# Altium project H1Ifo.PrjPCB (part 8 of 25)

## Sheet IfoIsc3.SchDoc: D1800185
size C; Engineer: Daniel Sigg; DocumentNumber: 7; Revision: 4; SheetNumber: 7; SheetTotal: 11
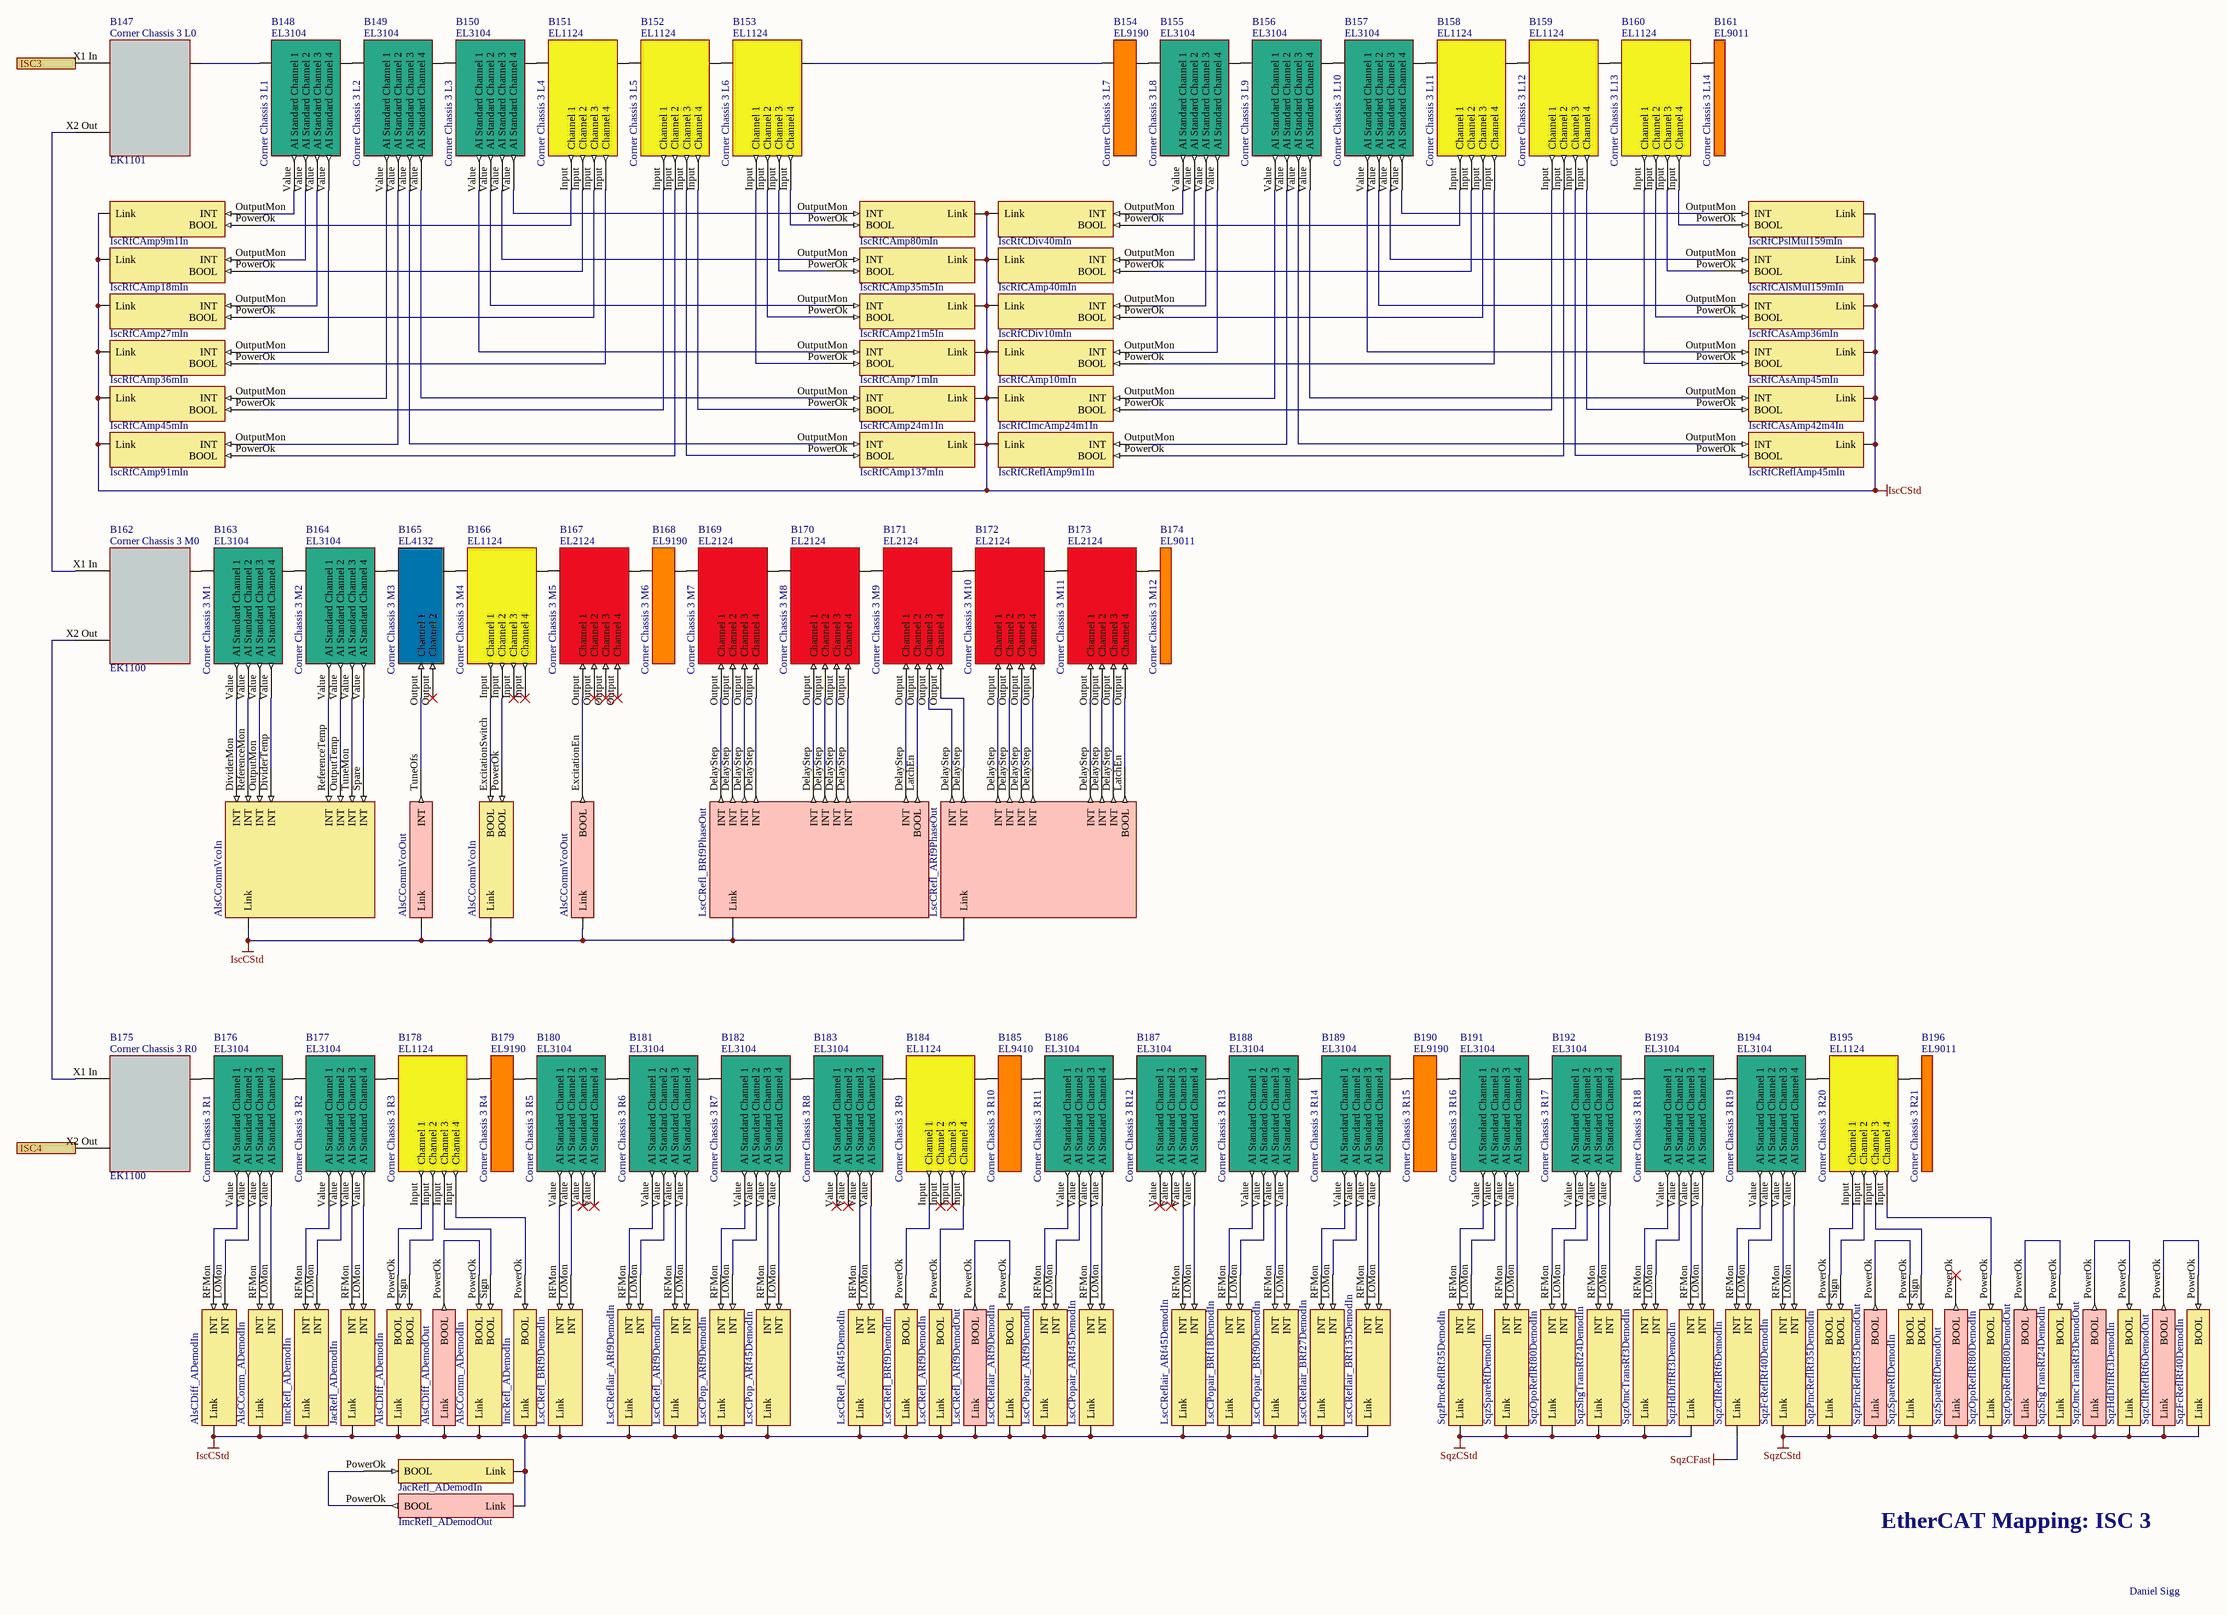
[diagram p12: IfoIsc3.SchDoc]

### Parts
B147  Corner Chassis 3 L0  Part Number: EK1101  (mechanical)
B148  Corner Chassis 3 L1  Part Number: EL3104  (mechanical)
B149  Corner Chassis 3 L2  Part Number: EL3104  (mechanical)
B150  Corner Chassis 3 L3  Part Number: EL3104  (mechanical)
B151  Corner Chassis 3 L4  Part Number: EL1124  (mechanical)
B152  Corner Chassis 3 L5  Part Number: EL1124  (mechanical)
B153  Corner Chassis 3 L6  Part Number: EL1124  (mechanical)
B154  Corner Chassis 3 L7  Part Number: EL9190  (mechanical)
B155  Corner Chassis 3 L8  Part Number: EL3104  (mechanical)
B156  Corner Chassis 3 L9  Part Number: EL3104  (mechanical)
B157  Corner Chassis 3 L10  Part Number: EL3104  (mechanical)
B158  Corner Chassis 3 L11  Part Number: EL1124  (mechanical)
B159  Corner Chassis 3 L12  Part Number: EL1124  (mechanical)
B160  Corner Chassis 3 L13  Part Number: EL1124  (mechanical)
B161  Corner Chassis 3 L14  Part Number: EL9011  (mechanical)
B162  Corner Chassis 3 M0  Part Number: EK1100  (mechanical)
B163  Corner Chassis 3 M1  Part Number: EL3104  (mechanical)
B164  Corner Chassis 3 M2  Part Number: EL3104  (mechanical)
B165  Corner Chassis 3 M3  Part Number: EL4132  (mechanical)
B166  Corner Chassis 3 M4  Part Number: EL1124  (mechanical)
B167  Corner Chassis 3 M5  Part Number: EL2124  (mechanical)
B168  Corner Chassis 3 M6  Part Number: EL9190  (mechanical)
B169  Corner Chassis 3 M7  Part Number: EL2124  (mechanical)
B170  Corner Chassis 3 M8  Part Number: EL2124  (mechanical)
B171  Corner Chassis 3 M9  Part Number: EL2124  (mechanical)
B172  Corner Chassis 3 M10  Part Number: EL2124  (mechanical)
B173  Corner Chassis 3 M11  Part Number: EL2124  (mechanical)
B174  Corner Chassis 3 M12  Part Number: EL9011  (mechanical)
B175  Corner Chassis 3 R0  Part Number: EK1100  (mechanical)
B176  Corner Chassis 3 R1  Part Number: EL3104  (mechanical)
B177  Corner Chassis 3 R2  Part Number: EL3104  (mechanical)
B178  Corner Chassis 3 R3  Part Number: EL1124  (mechanical)
B179  Corner Chassis 3 R4  Part Number: EL9190  (mechanical)
B180  Corner Chassis 3 R5  Part Number: EL3104  (mechanical)
B181  Corner Chassis 3 R6  Part Number: EL3104  (mechanical)
B182  Corner Chassis 3 R7  Part Number: EL3104  (mechanical)
B183  Corner Chassis 3 R8  Part Number: EL3104  (mechanical)
B184  Corner Chassis 3 R9  Part Number: EL1124  (mechanical)
B185  Corner Chassis 3 R10  Part Number: EL9410  (mechanical)
B186  Corner Chassis 3 R11  Part Number: EL3104  (mechanical)
B187  Corner Chassis 3 R12  Part Number: EL3104  (mechanical)
B188  Corner Chassis 3 R13  Part Number: EL3104  (mechanical)
B189  Corner Chassis 3 R14  Part Number: EL3104  (mechanical)
B190  Corner Chassis 3 R15  Part Number: EL9190  (mechanical)
B191  Corner Chassis 3 R16  Part Number: EL3104  (mechanical)
B192  Corner Chassis 3 R17  Part Number: EL3104  (mechanical)
B193  Corner Chassis 3 R18  Part Number: EL3104  (mechanical)
B194  Corner Chassis 3 R19  Part Number: EL3104  (mechanical)
B195  Corner Chassis 3 R20  Part Number: EL1124  (mechanical)
B196  Corner Chassis 3 R21  Part Number: EL9011  (mechanical)
V125  AlsCDiff_ADemodIn  (parts A,B of 2)  (no BOM)
V126  AlsCComm_ADemodIn  (parts A,B of 2)  (no BOM)
V127  ImcRefl_ADemodIn  (parts A,B of 2)  (no BOM)
V128  JacRefl_ADemodIn  (parts A,B of 2)  (no BOM)
V131  LscCReflair_ARf9DemodIn  (parts A,B of 2)  (no BOM)
V132  LscCRefl_ARf9DemodIn  (parts A,B of 2)  (no BOM)
V149  AlsCCommVcoIn  (parts A,B of 2)  (no BOM)
V153  SqzOpoReflRf80DemodIn  (parts A,B of 2)  (no BOM)
V154  SqzShgTransRf24DemodIn  (parts A,B of 2)  (no BOM)
V169  SqzHdDiffRf3DemodIn  (parts A,B of 2)  (no BOM)
V171  SqzFcReflRf40DemodIn  (parts A,B of 2)  (no BOM)
V210  IscRfCAmp9m1In  (no BOM)
V227  IscRfCAmp80mIn  (no BOM)
V236  IscRfCDiv40mIn  (no BOM)
V237  IscRfCPslMul159mIn  (no BOM)
V239  IscRfCAmp18mIn  (no BOM)
V240  IscRfCAmp35m5In  (no BOM)
V241  IscRfCAmp40mIn  (no BOM)
V242  IscRfCAlsMul159mIn  (no BOM)
V243  IscRfCAmp27mIn  (no BOM)
V244  IscRfCAmp21m5In  (no BOM)
V245  IscRfCDiv10mIn  (no BOM)
V246  IscRfCAsAmp36mIn  (no BOM)
V247  IscRfCAmp36mIn  (no BOM)
V248  IscRfCAmp71mIn  (no BOM)
V249  IscRfCAmp10mIn  (no BOM)
V250  IscRfCAsAmp45mIn  (no BOM)
V251  IscRfCAmp45mIn  (no BOM)
V252  IscRfCAmp24m1In  (no BOM)
V253  IscRfCImcAmp24m1In  (no BOM)
V254  IscRfCAsAmp42m4In  (no BOM)
V255  IscRfCAmp91mIn  (no BOM)
V256  IscRfCAmp137mIn  (no BOM)
V257  IscRfCReflAmp9m1In  (no BOM)
V260  IscRfCReflAmp45mIn  (no BOM)
V261  AlsCCommVcoOut  (parts A,B of 2)  (no BOM)
V264  LscCRefl_BRf9PhaseOut  (no BOM)
V265  LscCRefl_ARf9PhaseOut  (no BOM)
V266  AlsCDiff_ADemodOut  (no BOM)
V267  ImcRefl_ADemodOut  (no BOM)
V268  LscCPop_ARf9DemodIn  (no BOM)
V269  LscCPop_ARf45DemodIn  (no BOM)
V270  LscCRefl_ARf45DemodIn  (no BOM)
V271  LscCRefl_ARf9DemodOut  (no BOM)
V280  LscCPopair_ARf9DemodIn  (no BOM)
V281  LscCPopair_ARf45DemodIn  (no BOM)
V282  LscCReflair_ARf45DemodIn  (no BOM)
V283  LscCPopair_BRf18DemodIn  (no BOM)
V284  LscCPopair_BRf90DemodIn  (no BOM)
V285  LscCReflair_BRf27DemodIn  (no BOM)
V286  LscCReflair_BRf135DemodIn  (no BOM)
V287  SqzOmcTransRf3DemodIn  (no BOM)
V288  SqzClfReflRf6DemodIn  (no BOM)
V293  SqzPmcReflRf35DemodOut  (no BOM)
V294  SqzSpareRfDemodOut  (no BOM)
V295  SqzOpoReflRf80DemodOut  (no BOM)
V296  SqzOmcTransRf3DemodOut  (no BOM)
V299  SqzClfReflRf6DemodOut  (no BOM)
V680  SqzPmcReflRf35DemodIn  (parts A,B of 2)  (no BOM)
V681  SqzSpareRfDemodIn  (parts A,B of 2)  (no BOM)
V876  LscCRefl_BRf9DemodIn  (parts A,B of 2)  (no BOM)

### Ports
ISC3, ISC4

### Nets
IscCStd: V125.0(Link) V125.1(Link) V126.0(Link) V126.1(Link) V127.0(Link) V127.1(Link) V128.0(Link) V128.1(Link) V131.0(Link) V131.1(Link) V132.0(Link) V132.1(Link) V149.0(Link) V149.1(Link) V210.?1(Link) V227.?1(Link) V236.?1(Link) V237.?1(Link) V239.?1(Link) V240.?1(Link) V241.?1(Link) V242.?1(Link) V243.?1(Link) V244.?1(Link) V245.?1(Link) V246.?1(Link) V247.?1(Link) V248.?1(Link) V249.?1(Link) V250.?1(Link) V251.?1(Link) V252.?1(Link) V253.?1(Link) V254.?1(Link) V255.?1(Link) V256.?1(Link) V257.?1(Link) V260.?1(Link) V261.0(Link) V261.1(Link) V264.?1(Link) V265.?1(Link) V266.?1(Link) V267.?1(Link) V268.0(Link) V269.0(Link) V270.0(Link) V271.?1(Link) V280.0(Link) V281.0(Link) V282.0(Link) V283.0(Link) V284.0(Link) V285.0(Link) V286.0(Link) V876.0(Link) V876.1(Link)
SqzCFast: V288.0(Link)
SqzCStd: V153.0(Link) V153.1(Link) V154.0(Link) V154.1(Link) V169.0(Link) V169.1(Link) V171.0(Link) V171.1(Link) V287.0(Link) V293.?1(Link) V294.?1(Link) V295.?1(Link) V296.?1(Link) V299.?1(Link) V680.0(Link) V680.1(Link) V681.0(Link) V681.1(Link)
NetB107_X2 Out: B147.X1_In(A) ; port ISC3
NetB147_Ebus: B147.Ebus(B) B148.Ebus(A)
NetB147_X2 Out: B147.X2_Out(C) B162.X1_In(A)
NetB148_Ebus: B148.Ebus(B) B149.Ebus(A)
NetB148_Value: B148.Value(AI_Standard_Channel_1) V210.OutputMon(INT)
NetB148_Value: B148.Value(AI_Standard_Channel_2) V239.OutputMon(INT)  [a separate net that carries the same name]
NetB148_Value: B148.Value(AI_Standard_Channel_3) V243.OutputMon(INT)  [a separate net that carries the same name]
NetB148_Value: B148.Value(AI_Standard_Channel_4) V247.OutputMon(INT)  [a separate net that carries the same name]
NetB149_Ebus: B149.Ebus(B) B150.Ebus(A)
NetB149_Value: B149.Value(AI_Standard_Channel_1) V251.OutputMon(INT)
NetB149_Value: B149.Value(AI_Standard_Channel_2) V255.OutputMon(INT)  [a separate net that carries the same name]
NetB149_Value: B149.Value(AI_Standard_Channel_3) V256.OutputMon(INT)  [a separate net that carries the same name]
NetB149_Value: B149.Value(AI_Standard_Channel_4) V252.OutputMon(INT)  [a separate net that carries the same name]
NetB150_Ebus: B150.Ebus(B) B151.Ebus(A)
NetB150_Value: B150.Value(AI_Standard_Channel_1) V248.OutputMon(INT)
NetB150_Value: B150.Value(AI_Standard_Channel_2) V244.OutputMon(INT)  [a separate net that carries the same name]
NetB150_Value: B150.Value(AI_Standard_Channel_3) V240.OutputMon(INT)  [a separate net that carries the same name]
NetB150_Value: B150.Value(AI_Standard_Channel_4) V227.OutputMon(INT)  [a separate net that carries the same name]
NetB151_Ebus: B151.Ebus(B) B152.Ebus(A)
NetB151_Input: B151.Input(Channel_1) V210.PowerOk(BOOL)
NetB151_Input: B151.Input(Channel_2) V239.PowerOk(BOOL)  [a separate net that carries the same name]
NetB151_Input: B151.Input(Channel_3) V243.PowerOk(BOOL)  [a separate net that carries the same name]
NetB151_Input: B151.Input(Channel_4) V247.PowerOk(BOOL)  [a separate net that carries the same name]
NetB152_Ebus: B152.Ebus(B) B153.Ebus(A)
NetB152_Input: B152.Input(Channel_1) V251.PowerOk(BOOL)
NetB152_Input: B152.Input(Channel_2) V255.PowerOk(BOOL)  [a separate net that carries the same name]
NetB152_Input: B152.Input(Channel_3) V256.PowerOk(BOOL)  [a separate net that carries the same name]
NetB152_Input: B152.Input(Channel_4) V252.PowerOk(BOOL)  [a separate net that carries the same name]
NetB153_Ebus: B153.Ebus(B) B154.Ebus(A)
NetB153_Input: B153.Input(Channel_1) V248.PowerOk(BOOL)
NetB153_Input: B153.Input(Channel_2) V244.PowerOk(BOOL)  [a separate net that carries the same name]
NetB153_Input: B153.Input(Channel_3) V240.PowerOk(BOOL)  [a separate net that carries the same name]
NetB153_Input: B153.Input(Channel_4) V227.PowerOk(BOOL)  [a separate net that carries the same name]
NetB154_Ebus: B154.Ebus(B) B155.Ebus(A)
NetB155_Ebus: B155.Ebus(B) B156.Ebus(A)
NetB155_Value: B155.Value(AI_Standard_Channel_1) V236.OutputMon(INT)
NetB155_Value: B155.Value(AI_Standard_Channel_2) V241.OutputMon(INT)  [a separate net that carries the same name]
NetB155_Value: B155.Value(AI_Standard_Channel_3) V245.OutputMon(INT)  [a separate net that carries the same name]
NetB155_Value: B155.Value(AI_Standard_Channel_4) V249.OutputMon(INT)  [a separate net that carries the same name]
NetB156_Ebus: B156.Ebus(B) B157.Ebus(A)
NetB156_Value: B156.Value(AI_Standard_Channel_1) V253.OutputMon(INT)
NetB156_Value: B156.Value(AI_Standard_Channel_2) V257.OutputMon(INT)  [a separate net that carries the same name]
NetB156_Value: B156.Value(AI_Standard_Channel_3) V260.OutputMon(INT)  [a separate net that carries the same name]
NetB156_Value: B156.Value(AI_Standard_Channel_4) V254.OutputMon(INT)  [a separate net that carries the same name]
NetB157_Ebus: B157.Ebus(B) B158.Ebus(A)
NetB157_Value: B157.Value(AI_Standard_Channel_1) V250.OutputMon(INT)
NetB157_Value: B157.Value(AI_Standard_Channel_2) V246.OutputMon(INT)  [a separate net that carries the same name]
NetB157_Value: B157.Value(AI_Standard_Channel_3) V242.OutputMon(INT)  [a separate net that carries the same name]
NetB157_Value: B157.Value(AI_Standard_Channel_4) V237.OutputMon(INT)  [a separate net that carries the same name]
NetB158_Ebus: B158.Ebus(B) B159.Ebus(A)
NetB158_Input: B158.Input(Channel_1) V236.PowerOk(BOOL)
NetB158_Input: B158.Input(Channel_2) V241.PowerOk(BOOL)  [a separate net that carries the same name]
NetB158_Input: B158.Input(Channel_3) V245.PowerOk(BOOL)  [a separate net that carries the same name]
NetB158_Input: B158.Input(Channel_4) V249.PowerOk(BOOL)  [a separate net that carries the same name]
NetB159_Ebus: B159.Ebus(B) B160.Ebus(A)
NetB159_Input: B159.Input(Channel_1) V253.PowerOk(BOOL)
NetB159_Input: B159.Input(Channel_2) V257.PowerOk(BOOL)  [a separate net that carries the same name]
NetB159_Input: B159.Input(Channel_3) V260.PowerOk(BOOL)  [a separate net that carries the same name]
NetB159_Input: B159.Input(Channel_4) V254.PowerOk(BOOL)  [a separate net that carries the same name]
NetB160_Ebus: B160.Ebus(B) B161.Ebus(A)
NetB160_Input: B160.Input(Channel_1) V250.PowerOk(BOOL)
NetB160_Input: B160.Input(Channel_2) V246.PowerOk(BOOL)  [a separate net that carries the same name]
NetB160_Input: B160.Input(Channel_3) V242.PowerOk(BOOL)  [a separate net that carries the same name]
NetB160_Input: B160.Input(Channel_4) V237.PowerOk(BOOL)  [a separate net that carries the same name]
NetB162_Ebus: B162.Ebus(B) B163.Ebus(A)
NetB162_X2 Out: B162.X2_Out(C) B175.X1_In(A)
NetB163_Ebus: B163.Ebus(B) B164.Ebus(A)
NetB163_Value: B163.Value(AI_Standard_Channel_1) V149.DividerMon(INT)
NetB163_Value: B163.Value(AI_Standard_Channel_2) V149.ReferenceMon(INT)  [a separate net that carries the same name]
NetB163_Value: B163.Value(AI_Standard_Channel_3) V149.OutputMon(INT)  [a separate net that carries the same name]
NetB163_Value: B163.Value(AI_Standard_Channel_4) V149.DividerTemp(INT)  [a separate net that carries the same name]
NetB164_Ebus: B164.Ebus(B) B165.Ebus(A)
NetB164_Value: B164.Value(AI_Standard_Channel_1) V149.ReferenceTemp(INT)
NetB164_Value: B164.Value(AI_Standard_Channel_2) V149.OutputTemp(INT)  [a separate net that carries the same name]
NetB164_Value: B164.Value(AI_Standard_Channel_3) V149.TuneMon(INT)  [a separate net that carries the same name]
NetB164_Value: B164.Value(AI_Standard_Channel_4) V149.Spare(INT)  [a separate net that carries the same name]
NetB165_Ebus: B165.Ebus(B) B166.Ebus(A)
NetB165_Output: B165.Output(Channel_1) V261.TuneOfs(INT)
NetB166_Ebus: B166.Ebus(B) B167.Ebus(A)
NetB166_Input: B166.Input(Channel_1) V149.ExcitationSwitch(BOOL)
NetB166_Input: B166.Input(Channel_2) V149.PowerOk(BOOL)  [a separate net that carries the same name]
NetB167_Ebus: B167.Ebus(B) B168.Ebus(A)
NetB167_Output: B167.Output(Channel_1) V261.ExcitationEn(BOOL)
NetB168_Ebus: B168.Ebus(B) B169.Ebus(A)
NetB169_Ebus: B169.Ebus(B) B170.Ebus(A)
NetB169_Output: B169.Output(Channel_1) V264.DelayStep(INT)
NetB169_Output: B169.Output(Channel_2) V264.DelayStep(INT)  [a separate net that carries the same name]
NetB169_Output: B169.Output(Channel_3) V264.DelayStep(INT)  [a separate net that carries the same name]
NetB169_Output: B169.Output(Channel_4) V264.DelayStep(INT)  [a separate net that carries the same name]
NetB170_Ebus: B170.Ebus(B) B171.Ebus(A)
NetB170_Output: B170.Output(Channel_1) V264.DelayStep(INT)
NetB170_Output: B170.Output(Channel_2) V264.DelayStep(INT)  [a separate net that carries the same name]
NetB170_Output: B170.Output(Channel_3) V264.DelayStep(INT)  [a separate net that carries the same name]
NetB170_Output: B170.Output(Channel_4) V264.DelayStep(INT)  [a separate net that carries the same name]
NetB171_Ebus: B171.Ebus(B) B172.Ebus(A)
NetB171_Output: B171.Output(Channel_1) V264.DelayStep(INT)
NetB171_Output: B171.Output(Channel_2) V264.LatchEn(BOOL)  [a separate net that carries the same name]
NetB171_Output: B171.Output(Channel_3) V265.DelayStep(INT)  [a separate net that carries the same name]
NetB171_Output: B171.Output(Channel_4) V265.DelayStep(INT)  [a separate net that carries the same name]
NetB172_Ebus: B172.Ebus(B) B173.Ebus(A)
NetB172_Output: B172.Output(Channel_1) V265.DelayStep(INT)
NetB172_Output: B172.Output(Channel_2) V265.DelayStep(INT)  [a separate net that carries the same name]
NetB172_Output: B172.Output(Channel_3) V265.DelayStep(INT)  [a separate net that carries the same name]
NetB172_Output: B172.Output(Channel_4) V265.DelayStep(INT)  [a separate net that carries the same name]
NetB173_Ebus: B173.Ebus(B) B174.Ebus(A)
NetB173_Output: B173.Output(Channel_1) V265.DelayStep(INT)
NetB173_Output: B173.Output(Channel_2) V265.DelayStep(INT)  [a separate net that carries the same name]
NetB173_Output: B173.Output(Channel_3) V265.DelayStep(INT)  [a separate net that carries the same name]
NetB173_Output: B173.Output(Channel_4) V265.LatchEn(BOOL)  [a separate net that carries the same name]
NetB175_Ebus: B175.Ebus(B) B176.Ebus(A)
NetB175_X2 Out: B175.X2_Out(C) ; port ISC4
NetB176_Ebus: B176.Ebus(B) B177.Ebus(A)
NetB176_Value: B176.Value(AI_Standard_Channel_1) V125.RFMon(INT)
NetB176_Value: B176.Value(AI_Standard_Channel_2) V125.LOMon(INT)  [a separate net that carries the same name]
NetB176_Value: B176.Value(AI_Standard_Channel_3) V126.RFMon(INT)  [a separate net that carries the same name]
NetB176_Value: B176.Value(AI_Standard_Channel_4) V126.LOMon(INT)  [a separate net that carries the same name]
NetB177_Ebus: B177.Ebus(B) B178.Ebus(A)
NetB177_Value: B177.Value(AI_Standard_Channel_1) V127.RFMon(INT)
NetB177_Value: B177.Value(AI_Standard_Channel_2) V127.LOMon(INT)  [a separate net that carries the same name]
NetB177_Value: B177.Value(AI_Standard_Channel_3) V128.RFMon(INT)  [a separate net that carries the same name]
NetB177_Value: B177.Value(AI_Standard_Channel_4) V128.LOMon(INT)  [a separate net that carries the same name]
NetB178_Ebus: B178.Ebus(B) B179.Ebus(A)
NetB178_Input: B178.Input(Channel_1) V125.PowerOk(BOOL)
NetB178_Input: B178.Input(Channel_2) V125.Sign(BOOL)  [a separate net that carries the same name]
NetB178_Input: B178.Input(Channel_3) V126.Sign(BOOL)  [a separate net that carries the same name]
NetB178_Input: B178.Input(Channel_4) V127.PowerOk(BOOL)  [a separate net that carries the same name]
NetB179_Ebus: B179.Ebus(B) B180.Ebus(A)
NetB180_Ebus: B180.Ebus(B) B181.Ebus(A)
NetB180_Value: B180.Value(AI_Standard_Channel_1) V876.RFMon(INT)
NetB180_Value: B180.Value(AI_Standard_Channel_2) V876.LOMon(INT)  [a separate net that carries the same name]
NetB181_Ebus: B181.Ebus(B) B182.Ebus(A)
NetB181_Value: B181.Value(AI_Standard_Channel_1) V131.RFMon(INT)
NetB181_Value: B181.Value(AI_Standard_Channel_2) V131.LOMon(INT)  [a separate net that carries the same name]
NetB181_Value: B181.Value(AI_Standard_Channel_3) V132.RFMon(INT)  [a separate net that carries the same name]
NetB181_Value: B181.Value(AI_Standard_Channel_4) V132.LOMon(INT)  [a separate net that carries the same name]
NetB182_Ebus: B182.Ebus(B) B183.Ebus(A)
NetB182_Value: B182.Value(AI_Standard_Channel_1) V268.RFMon(INT)
NetB182_Value: B182.Value(AI_Standard_Channel_2) V268.LOMon(INT)  [a separate net that carries the same name]
NetB182_Value: B182.Value(AI_Standard_Channel_3) V269.RFMon(INT)  [a separate net that carries the same name]
NetB182_Value: B182.Value(AI_Standard_Channel_4) V269.LOMon(INT)  [a separate net that carries the same name]
NetB183_Ebus: B183.Ebus(B) B184.Ebus(A)
NetB183_Value: B183.Value(AI_Standard_Channel_1) V270.RFMon(INT)
NetB183_Value: B183.Value(AI_Standard_Channel_4) V270.LOMon(INT)  [a separate net that carries the same name]
NetB184_Ebus: B184.Ebus(B) B185.Ebus(A)
NetB184_Input: B184.Input(Channel_1) V876.PowerOk(BOOL)
NetB184_Input: B184.Input(Channel_4) V132.PowerOk(BOOL)  [a separate net that carries the same name]
NetB185_Ebus: B185.Ebus(B) B186.Ebus(A)
NetB186_Ebus: B186.Ebus(B) B187.Ebus(A)
NetB186_Value: B186.Value(AI_Standard_Channel_1) V280.RFMon(INT)
NetB186_Value: B186.Value(AI_Standard_Channel_2) V280.LOMon(INT)  [a separate net that carries the same name]
NetB186_Value: B186.Value(AI_Standard_Channel_3) V281.RFMon(INT)  [a separate net that carries the same name]
NetB186_Value: B186.Value(AI_Standard_Channel_4) V281.LOMon(INT)  [a separate net that carries the same name]
NetB187_Ebus: B187.Ebus(B) B188.Ebus(A)
NetB187_Value: B187.Value(AI_Standard_Channel_1) V282.RFMon(INT)
NetB187_Value: B187.Value(AI_Standard_Channel_4) V282.LOMon(INT)  [a separate net that carries the same name]
NetB188_Ebus: B188.Ebus(B) B189.Ebus(A)
NetB188_Value: B188.Value(AI_Standard_Channel_1) V283.RFMon(INT)
NetB188_Value: B188.Value(AI_Standard_Channel_2) V283.LOMon(INT)  [a separate net that carries the same name]
NetB188_Value: B188.Value(AI_Standard_Channel_3) V284.RFMon(INT)  [a separate net that carries the same name]
NetB188_Value: B188.Value(AI_Standard_Channel_4) V284.LOMon(INT)  [a separate net that carries the same name]
NetB189_Ebus: B189.Ebus(B) B190.Ebus(A)
NetB189_Value: B189.Value(AI_Standard_Channel_1) V285.RFMon(INT)
NetB189_Value: B189.Value(AI_Standard_Channel_2) V285.LOMon(INT)  [a separate net that carries the same name]
NetB189_Value: B189.Value(AI_Standard_Channel_3) V286.RFMon(INT)  [a separate net that carries the same name]
NetB189_Value: B189.Value(AI_Standard_Channel_4) V286.LOMon(INT)  [a separate net that carries the same name]
NetB190_Ebus: B190.Ebus(B) B191.Ebus(A)
NetB191_Ebus: B191.Ebus(B) B192.Ebus(A)
NetB191_Value: B191.Value(AI_Standard_Channel_1) V680.RFMon(INT)
NetB191_Value: B191.Value(AI_Standard_Channel_2) V680.LOMon(INT)  [a separate net that carries the same name]
NetB191_Value: B191.Value(AI_Standard_Channel_3) V681.RFMon(INT)  [a separate net that carries the same name]
NetB191_Value: B191.Value(AI_Standard_Channel_4) V681.LOMon(INT)  [a separate net that carries the same name]
NetB192_Ebus: B192.Ebus(B) B193.Ebus(A)
NetB192_Value: B192.Value(AI_Standard_Channel_1) V153.RFMon(INT)
NetB192_Value: B192.Value(AI_Standard_Channel_2) V153.LOMon(INT)  [a separate net that carries the same name]
NetB192_Value: B192.Value(AI_Standard_Channel_3) V154.RFMon(INT)  [a separate net that carries the same name]
NetB192_Value: B192.Value(AI_Standard_Channel_4) V154.LOMon(INT)  [a separate net that carries the same name]
NetB193_Ebus: B193.Ebus(B) B194.Ebus(A)
NetB193_Value: B193.Value(AI_Standard_Channel_1) V287.RFMon(INT)
NetB193_Value: B193.Value(AI_Standard_Channel_2) V287.LOMon(INT)  [a separate net that carries the same name]
NetB193_Value: B193.Value(AI_Standard_Channel_3) V169.RFMon(INT)  [a separate net that carries the same name]
NetB193_Value: B193.Value(AI_Standard_Channel_4) V169.LOMon(INT)  [a separate net that carries the same name]
NetB194_Ebus: B194.Ebus(B) B195.Ebus(A)
NetB194_Value: B194.Value(AI_Standard_Channel_1) V288.RFMon(INT)
NetB194_Value: B194.Value(AI_Standard_Channel_2) V288.LOMon(INT)  [a separate net that carries the same name]
NetB194_Value: B194.Value(AI_Standard_Channel_3) V171.RFMon(INT)  [a separate net that carries the same name]
NetB194_Value: B194.Value(AI_Standard_Channel_4) V171.LOMon(INT)  [a separate net that carries the same name]
NetB195_Ebus: B195.Ebus(B) B196.Ebus(A)
NetB195_Input: B195.Input(Channel_1) V680.PowerOk(BOOL)
NetB195_Input: B195.Input(Channel_2) V680.Sign(BOOL)  [a separate net that carries the same name]
NetB195_Input: B195.Input(Channel_3) V681.Sign(BOOL)  [a separate net that carries the same name]
NetB195_Input: B195.Input(Channel_4) V153.PowerOk(BOOL)  [a separate net that carries the same name]
NetV126_PowerOk: V126.PowerOk(BOOL) V266.PowerOk(BOOL)
NetV128_PowerOk: V128.PowerOk(BOOL) V267.PowerOk(BOOL)
NetV131_PowerOk: V131.PowerOk(BOOL) V271.PowerOk(BOOL)
NetV154_PowerOk: V154.PowerOk(BOOL) V295.PowerOk(BOOL)
NetV169_PowerOk: V169.PowerOk(BOOL) V296.PowerOk(BOOL)
NetV171_PowerOk: V171.PowerOk(BOOL) V299.PowerOk(BOOL)
NetV293_PowerOk: V293.PowerOk(BOOL) V681.PowerOk(BOOL)

Not connected (* = marked no-connect by the designer): V294 PowerOk(BOOL)*

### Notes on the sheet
- EtherCAT Mapping: ISC 3
- Daniel Sigg

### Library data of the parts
B147 = CouplerEK1101: EtherCAT Coupler; Rail: Left; BoxNextB: STJAAMXH; BoxNextC: KKINGDKM; BoxPrev: JDBXWTJH; PortPrevFull: 1085/C; PortPrevShort: C 'X2 Out'; Fullname: TIID^Vertex ISC (EtherCAT)^Corner Chassis 3 L0 (EK1101); BoxPorts: Junction; BoxAddr: 1110; Disabled: False
B148 = TerminalEL3104: EtherCAT Terminal EL3104 4-chn Analog Input; Rail: Left; BoxNextB: HEQGDFWQ; BoxPrev: OSFIYXRO; PortPrevFull: 1110/B; PortPrevShort: B; Fullname: TIID^Vertex ISC (EtherCAT)^Corner Chassis 3 L0 (EK1101)^Corner Chassis 3 L1 (EL3104); BoxAddr: 1111; Disabled: False
B149 = TerminalEL3104: EtherCAT Terminal EL3104 4-chn Analog Input; Rail: Left; BoxNextB: HRPNLCIR; BoxPrev: STJAAMXH; PortPrevFull: 1111/B; PortPrevShort: B; Fullname: TIID^Vertex ISC (EtherCAT)^Corner Chassis 3 L0 (EK1101)^Corner Chassis 3 L2 (EL3104); BoxAddr: 1112; Disabled: False
B150 = TerminalEL3104: EtherCAT Terminal EL3104 4-chn Analog Input; Rail: Left; BoxNextB: NKXFQBQN; BoxPrev: HEQGDFWQ; PortPrevFull: 1112/B; PortPrevShort: B; Fullname: TIID^Vertex ISC (EtherCAT)^Corner Chassis 3 L0 (EK1101)^Corner Chassis 3 L3 (EL3104); BoxAddr: 1113; Disabled: False
B151 = TerminalEL1124: EtherCAT Terminal EL1124 4-chn Digital Input; Rail: Left; BoxNextB: HTAQRIMN; BoxPrev: HRPNLCIR; PortPrevFull: 1113/B; PortPrevShort: B; Fullname: TIID^Vertex ISC (EtherCAT)^Corner Chassis 3 L0 (EK1101)^Corner Chassis 3 L4 (EL1124); BoxAddr: 1114; Disabled: False
B152 = TerminalEL1124: EtherCAT Terminal EL1124 4-chn Digital Input; Rail: Left; BoxNextB: ROHXDRMC; BoxPrev: NKXFQBQN; PortPrevFull: 1114/B; PortPrevShort: B; Fullname: TIID^Vertex ISC (EtherCAT)^Corner Chassis 3 L0 (EK1101)^Corner Chassis 3 L5 (EL1124); BoxAddr: 1115; Disabled: False
B153 = TerminalEL1124: EtherCAT Terminal EL1124 4-chn Digital Input; Rail: Left; BoxNextB: BSPGXCUF; BoxPrev: HTAQRIMN; PortPrevFull: 1115/B; PortPrevShort: B; Fullname: TIID^Vertex ISC (EtherCAT)^Corner Chassis 3 L0 (EK1101)^Corner Chassis 3 L6 (EL1124); BoxAddr: 1116; Disabled: False
B154 = TerminalEL9190: EtherCAT Terminal EL9190 Supply; BoxType: TerminalPassive; Rail: Left; BoxNextB: BGYCEJUN; BoxPrev: ROHXDRMC; PortPrevShort: B; Fullname: TIID^Vertex ISC (EtherCAT)^Corner Chassis 3 L0 (EK1101)^Corner Chassis 3 L7 (EL9190); Disabled: False
B155 = TerminalEL3104: EtherCAT Terminal EL3104 4-chn Analog Input; Rail: Left; BoxNextB: OJWJDJBW; BoxPrev: BSPGXCUF; PortPrevFull: 1116/B; PortPrevShort: B; Fullname: TIID^Vertex ISC (EtherCAT)^Corner Chassis 3 L0 (EK1101)^Corner Chassis 3 L8 (EL3104); BoxAddr: 1117; Disabled: False
B156 = TerminalEL3104: EtherCAT Terminal EL3104 4-chn Analog Input; Rail: Left; BoxNextB: ETDASMTA; BoxPrev: BGYCEJUN; PortPrevFull: 1117/B; PortPrevShort: B; Fullname: TIID^Vertex ISC (EtherCAT)^Corner Chassis 3 L0 (EK1101)^Corner Chassis 3 L9 (EL3104); BoxAddr: 1118; Disabled: False
B157 = TerminalEL3104: EtherCAT Terminal EL3104 4-chn Analog Input; Rail: Left; BoxNextB: XWQLUKDY; BoxPrev: OJWJDJBW; PortPrevFull: 1118/B; PortPrevShort: B; Fullname: TIID^Vertex ISC (EtherCAT)^Corner Chassis 3 L0 (EK1101)^Corner Chassis 3 L10 (EL3104); BoxAddr: 1119; Disabled: False
B158 = TerminalEL1124: EtherCAT Terminal EL1124 4-chn Digital Input; Rail: Left; BoxNextB: ASXRGKUP; BoxPrev: ETDASMTA; PortPrevFull: 1119/B; PortPrevShort: B; Fullname: TIID^Vertex ISC (EtherCAT)^Corner Chassis 3 L0 (EK1101)^Corner Chassis 3 L11 (EL1124); BoxAddr: 1120; Disabled: False
B159 = TerminalEL1124: EtherCAT Terminal EL1124 4-chn Digital Input; Rail: Left; BoxNextB: ACBXTXVL; BoxPrev: XWQLUKDY; PortPrevFull: 1120/B; PortPrevShort: B; Fullname: TIID^Vertex ISC (EtherCAT)^Corner Chassis 3 L0 (EK1101)^Corner Chassis 3 L12 (EL1124); BoxAddr: 1121; Disabled: False
B160 = TerminalEL1124: EtherCAT Terminal EL1124 4-chn Digital Input; Rail: Left; BoxNextB: XGATPXDO; BoxPrev: ASXRGKUP; PortPrevFull: 1121/B; PortPrevShort: B; Fullname: TIID^Vertex ISC (EtherCAT)^Corner Chassis 3 L0 (EK1101)^Corner Chassis 3 L13 (EL1124); BoxAddr: 1122; Disabled: False
B161 = TerminalEL9011: EtherCAT Terminal EL9011 End; BoxType: TerminalPassive; Rail: Left; BoxPrev: ACBXTXVL; PortPrevShort: B; Fullname: TIID^Vertex ISC (EtherCAT)^Corner Chassis 3 L0 (EK1101)^Corner Chassis 3 L14 (EL9011); Disabled: False
B162 = CouplerEK1100: EtherCAT Coupler; Rail: Middle; BoxNextB: CROUPSLF; BoxNextC: DISNVYMV; BoxPrev: OSFIYXRO; PortPrevFull: 1110/C; PortPrevShort: C 'X2 Out'; Fullname: TIID^Vertex ISC (EtherCAT)^Corner Chassis 3 M0 (EK1100); BoxPorts: Junction; BoxAddr: 1123; Disabled: False
B163 = TerminalEL3104: EtherCAT Terminal EL3104 4-chn Analog Input; Rail: Middle; BoxNextB: DNDPUAJY; BoxPrev: KKINGDKM; PortPrevFull: 1123/B; PortPrevShort: B; Fullname: TIID^Vertex ISC (EtherCAT)^Corner Chassis 3 M0 (EK1100)^Corner Chassis 3 M1 (EL3104); BoxAddr: 1124; Disabled: False
B164 = TerminalEL3104: EtherCAT Terminal EL3104 4-chn Analog Input; Rail: Middle; BoxNextB: QQQLAHUL; BoxPrev: CROUPSLF; PortPrevFull: 1124/B; PortPrevShort: B; Fullname: TIID^Vertex ISC (EtherCAT)^Corner Chassis 3 M0 (EK1100)^Corner Chassis 3 M2 (EL3104); BoxAddr: 1125; Disabled: False
B165 = TerminalEL4132: EtherCAT Terminal EL4132 2-chn Analog Ouput; Rail: Middle; BoxNextB: RKJVMMDE; BoxPrev: DNDPUAJY; PortPrevFull: 1125/B; PortPrevShort: B; Fullname: TIID^Vertex ISC (EtherCAT)^Corner Chassis 3 M0 (EK1100)^Corner Chassis 3 M3 (EL4132); BoxAddr: 1126; Disabled: False
B166 = TerminalEL1124: EtherCAT Terminal EL1124 4-chn Digital Input; Rail: Middle; BoxNextB: KJALUGED; BoxPrev: QQQLAHUL; PortPrevFull: 1126/B; PortPrevShort: B; Fullname: TIID^Vertex ISC (EtherCAT)^Corner Chassis 3 M0 (EK1100)^Corner Chassis 3 M4 (EL1124); BoxAddr: 1127; Disabled: False
B167 = TerminalEL2124: EtherCAT Terminal EL2124 4-chn Digital Ouput; Rail: Middle; BoxNextB: XDPFYTQL; BoxPrev: RKJVMMDE; PortPrevFull: 1127/B; PortPrevShort: B; Fullname: TIID^Vertex ISC (EtherCAT)^Corner Chassis 3 M0 (EK1100)^Corner Chassis 3 M5 (EL2124); BoxAddr: 1128; Disabled: False
B168 = TerminalEL9190: EtherCAT Terminal EL9190 Supply; BoxType: TerminalPassive; Rail: Middle; BoxNextB: KJJROUJM; BoxPrev: KJALUGED; PortPrevShort: B; Fullname: TIID^Vertex ISC (EtherCAT)^Corner Chassis 3 M0 (EK1100)^Corner Chassis 3 M6 (EL9190); Disabled: False
B169 = TerminalEL2124: EtherCAT Terminal EL2124 4-chn Digital Ouput; Rail: Middle; BoxNextB: OJFMRVHH; BoxPrev: XDPFYTQL; PortPrevFull: 1128/B; PortPrevShort: B; Fullname: TIID^Vertex ISC (EtherCAT)^Corner Chassis 3 M0 (EK1100)^Corner Chassis 3 M7 (EL2124); BoxAddr: 1129; Disabled: False
B170 = TerminalEL2124: EtherCAT Terminal EL2124 4-chn Digital Ouput; Rail: Middle; BoxNextB: TANRTAYG; BoxPrev: KJJROUJM; PortPrevFull: 1129/B; PortPrevShort: B; Fullname: TIID^Vertex ISC (EtherCAT)^Corner Chassis 3 M0 (EK1100)^Corner Chassis 3 M8 (EL2124); BoxAddr: 1130; Disabled: False
B171 = TerminalEL2124: EtherCAT Terminal EL2124 4-chn Digital Ouput; Rail: Middle; BoxNextB: GNVYIGRP; BoxPrev: OJFMRVHH; PortPrevFull: 1130/B; PortPrevShort: B; Fullname: TIID^Vertex ISC (EtherCAT)^Corner Chassis 3 M0 (EK1100)^Corner Chassis 3 M9 (EL2124); BoxAddr: 1131; Disabled: False
B172 = TerminalEL2124: EtherCAT Terminal EL2124 4-chn Digital Ouput; Rail: Middle; BoxNextB: OSIIXROS; BoxPrev: TANRTAYG; PortPrevFull: 1131/B; PortPrevShort: B; Fullname: TIID^Vertex ISC (EtherCAT)^Corner Chassis 3 M0 (EK1100)^Corner Chassis 3 M10 (EL2124); BoxAddr: 1132; Disabled: False
B173 = TerminalEL2124: EtherCAT Terminal EL2124 4-chn Digital Ouput; Rail: Middle; BoxNextB: HIXVVCXU; BoxPrev: GNVYIGRP; PortPrevFull: 1132/B; PortPrevShort: B; Fullname: TIID^Vertex ISC (EtherCAT)^Corner Chassis 3 M0 (EK1100)^Corner Chassis 3 M11 (EL2124); BoxAddr: 1133; Disabled: False
B174 = TerminalEL9011: EtherCAT Terminal EL9011 End; BoxType: TerminalPassive; Rail: Middle; BoxPrev: OSIIXROS; PortPrevShort: B; Fullname: TIID^Vertex ISC (EtherCAT)^Corner Chassis 3 M0 (EK1100)^Corner Chassis 3 M12 (EL9011); Disabled: False
B175 = CouplerEK1100: EtherCAT Coupler; Rail: Right; BoxNextB: BYRDTTUY; BoxNextC: YKWNQAOF; BoxPrev: KKINGDKM; PortPrevFull: 1123/C; PortPrevShort: C 'X2 Out'; Fullname: TIID^Vertex ISC (EtherCAT)^Corner Chassis 3 R0 (EK1100); BoxPorts: Junction; BoxAddr: 1134; Disabled: False
B176 = TerminalEL3104: EtherCAT Terminal EL3104 4-chn Analog Input; Rail: Right; BoxNextB: QMYPSGKK; BoxPrev: DISNVYMV; PortPrevFull: 1134/B; PortPrevShort: B; Fullname: TIID^Vertex ISC (EtherCAT)^Corner Chassis 3 R0 (EK1100)^Corner Chassis 3 R1 (EL3104); BoxAddr: 1135; Disabled: False
B177 = TerminalEL3104: EtherCAT Terminal EL3104 4-chn Analog Input; Rail: Right; BoxNextB: LKWAILEM; BoxPrev: BYRDTTUY; PortPrevFull: 1135/B; PortPrevShort: B; Fullname: TIID^Vertex ISC (EtherCAT)^Corner Chassis 3 R0 (EK1100)^Corner Chassis 3 R2 (EL3104); BoxAddr: 1136; Disabled: False
B178 = TerminalEL1124: EtherCAT Terminal EL1124 4-chn Digital Input; Rail: Right; BoxNextB: CORCEVAN; BoxPrev: QMYPSGKK; PortPrevFull: 1136/B; PortPrevShort: B; Fullname: TIID^Vertex ISC (EtherCAT)^Corner Chassis 3 R0 (EK1100)^Corner Chassis 3 R3 (EL1124); BoxAddr: 1137; Disabled: False
B179 = TerminalEL9190: EtherCAT Terminal EL9190 Supply; BoxType: TerminalPassive; Rail: Right; BoxNextB: ROFKPWIG; BoxPrev: LKWAILEM; PortPrevShort: B; Fullname: TIID^Vertex ISC (EtherCAT)^Corner Chassis 3 R0 (EK1100)^Corner Chassis 3 R4 (EL9190); Disabled: False
B180 = TerminalEL3104: EtherCAT Terminal EL3104 4-chn Analog Input; Rail: Right; BoxNextB: MDGXNCNX; BoxPrev: CORCEVAN; PortPrevFull: 1137/B; PortPrevShort: B; Fullname: TIID^Vertex ISC (EtherCAT)^Corner Chassis 3 R0 (EK1100)^Corner Chassis 3 R5 (EL3104); BoxAddr: 1138; Disabled: False
B181 = TerminalEL3104: EtherCAT Terminal EL3104 4-chn Analog Input; Rail: Right; BoxNextB: FROOTMMI; BoxPrev: ROFKPWIG; PortPrevFull: 1138/B; PortPrevShort: B; Fullname: TIID^Vertex ISC (EtherCAT)^Corner Chassis 3 R0 (EK1100)^Corner Chassis 3 R6 (EL3104); BoxAddr: 1139; Disabled: False
B182 = TerminalEL3104: EtherCAT Terminal EL3104 4-chn Analog Input; Rail: Right; BoxNextB: PIKDMSWF; BoxPrev: MDGXNCNX; PortPrevFull: 1139/B; PortPrevShort: B; Fullname: TIID^Vertex ISC (EtherCAT)^Corner Chassis 3 R0 (EK1100)^Corner Chassis 3 R7 (EL3104); BoxAddr: 1140; Disabled: False
B183 = TerminalEL3104: EtherCAT Terminal EL3104 4-chn Analog Input; Rail: Right; BoxNextB: CSUIWKEN; BoxPrev: FROOTMMI; PortPrevFull: 1140/B; PortPrevShort: B; Fullname: TIID^Vertex ISC (EtherCAT)^Corner Chassis 3 R0 (EK1100)^Corner Chassis 3 R8 (EL3104); BoxAddr: 1141; Disabled: False
B184 = TerminalEL1124: EtherCAT Terminal EL1124 4-chn Digital Input; Rail: Right; BoxNextB: AOONPOWA; BoxPrev: PIKDMSWF; PortPrevFull: 1141/B; PortPrevShort: B; Fullname: TIID^Vertex ISC (EtherCAT)^Corner Chassis 3 R0 (EK1100)^Corner Chassis 3 R9 (EL1124); BoxAddr: 1142; Disabled: False
B185 = TerminalEL9410: EtherCAT Terminal EL9410 Power; Rail: Right; BoxNextB: UJCNRJSR; BoxPrev: CSUIWKEN; PortPrevFull: 1142/B; PortPrevShort: B; Fullname: TIID^Vertex ISC (EtherCAT)^Corner Chassis 3 R0 (EK1100)^Corner Chassis 3 R10 (EL9410); BoxAddr: 1143; Disabled: False
B186 = TerminalEL3104: EtherCAT Terminal EL3104 4-chn Analog Input; Rail: Right; BoxNextB: FLFQSGUJ; BoxPrev: AOONPOWA; PortPrevFull: 1143/B; PortPrevShort: B; Fullname: TIID^Vertex ISC (EtherCAT)^Corner Chassis 3 R0 (EK1100)^Corner Chassis 3 R11 (EL3104); BoxAddr: 1144; Disabled: False
B187 = TerminalEL3104: EtherCAT Terminal EL3104 4-chn Analog Input; Rail: Right; BoxNextB: SXWUJAKP; BoxPrev: UJCNRJSR; PortPrevFull: 1144/B; PortPrevShort: B; Fullname: TIID^Vertex ISC (EtherCAT)^Corner Chassis 3 R0 (EK1100)^Corner Chassis 3 R12 (EL3104); BoxAddr: 1145; Disabled: False
B188 = TerminalEL3104: EtherCAT Terminal EL3104 4-chn Analog Input; Rail: Right; BoxNextB: LPNHHAGC; BoxPrev: FLFQSGUJ; PortPrevFull: 1145/B; PortPrevShort: B; Fullname: TIID^Vertex ISC (EtherCAT)^Corner Chassis 3 R0 (EK1100)^Corner Chassis 3 R13 (EL3104); BoxAddr: 1146; Disabled: False
B189 = TerminalEL3104: EtherCAT Terminal EL3104 4-chn Analog Input; Rail: Right; BoxNextB: MORWRCQN; BoxPrev: SXWUJAKP; PortPrevFull: 1146/B; PortPrevShort: B; Fullname: TIID^Vertex ISC (EtherCAT)^Corner Chassis 3 R0 (EK1100)^Corner Chassis 3 R14 (EL3104); BoxAddr: 1147; Disabled: False
B190 = TerminalEL9190: EtherCAT Terminal EL9190 Supply; BoxType: TerminalPassive; Rail: Right; BoxNextB: RKUWAVWN; BoxPrev: LPNHHAGC; PortPrevShort: B; Fullname: TIID^Vertex ISC (EtherCAT)^Corner Chassis 3 R0 (EK1100)^Corner Chassis 3 R15 (EL9190); Disabled: False
B191 = TerminalEL3104: EtherCAT Terminal EL3104 4-chn Analog Input; Rail: Right; BoxNextB: HJABMPYT; BoxPrev: MORWRCQN; PortPrevFull: 1147/B; PortPrevShort: B; Fullname: TIID^Vertex ISC (EtherCAT)^Corner Chassis 3 R0 (EK1100)^Corner Chassis 3 R16 (EL3104); BoxAddr: 1148; Disabled: False
B192 = TerminalEL3104: EtherCAT Terminal EL3104 4-chn Analog Input; Rail: Right; BoxNextB: TAQIWEFR; BoxPrev: RKUWAVWN; PortPrevFull: 1148/B; PortPrevShort: B; Fullname: TIID^Vertex ISC (EtherCAT)^Corner Chassis 3 R0 (EK1100)^Corner Chassis 3 R17 (EL3104); BoxAddr: 1149; Disabled: False
B193 = TerminalEL3104: EtherCAT Terminal EL3104 4-chn Analog Input; Rail: Right; BoxNextB: IYVDJRHL; BoxPrev: HJABMPYT; PortPrevFull: 1149/B; PortPrevShort: B; Fullname: TIID^Vertex ISC (EtherCAT)^Corner Chassis 3 R0 (EK1100)^Corner Chassis 3 R18 (EL3104); BoxAddr: 1150; Disabled: False
B194 = TerminalEL3104: EtherCAT Terminal EL3104 4-chn Analog Input; Rail: Right; BoxNextB: CKGFBYGB; BoxPrev: TAQIWEFR; PortPrevFull: 1150/B; PortPrevShort: B; Fullname: TIID^Vertex ISC (EtherCAT)^Corner Chassis 3 R0 (EK1100)^Corner Chassis 3 R19 (EL3104); BoxAddr: 1151; Disabled: False
B195 = TerminalEL1124: EtherCAT Terminal EL1124 4-chn Digital Input; Rail: Right; BoxNextB: TNDRAWOC; BoxPrev: IYVDJRHL; PortPrevFull: 1151/B; PortPrevShort: B; Fullname: TIID^Vertex ISC (EtherCAT)^Corner Chassis 3 R0 (EK1100)^Corner Chassis 3 R20 (EL1124); BoxAddr: 1152; Disabled: False
B196 = TerminalEL9011: EtherCAT Terminal EL9011 End; BoxType: TerminalPassive; Rail: Right; BoxPrev: CKGFBYGB; PortPrevShort: B; Fullname: TIID^Vertex ISC (EtherCAT)^Corner Chassis 3 R0 (EK1100)^Corner Chassis 3 R21 (EL9011); Disabled: False
V125 V126 = Demodulator_DemodulatorInStructSign: DemodulatorInStruct; BoxType: Variable; Instance: H1IscCorner Instance; PLC: H1IscCorner; Task: IscCStd
V127 V128 V131 V132 V876 = Demodulator_DemodulatorInStructOk: DemodulatorInStruct; BoxType: Variable; Instance: H1IscCorner Instance; PLC: H1IscCorner; Task: IscCStd
V149 = LowNoiseVco_LowNoiseVcoInStructB: LowNoiseVcoInStruct; BoxType: Variable; Instance: H1IscCorner Instance; PLC: H1IscCorner; Task: IscCStd
V153 V154 V169 V171 = Demodulator_DemodulatorInStructOk: DemodulatorInStruct; BoxType: Variable; Instance: H1SqzCorner Instance; PLC: H1SqzCorner; Task: SqzCStd
V210 V227 V236 V237 V239-V257 V260 = RFAmplifier_RFAmplifierInStruct: RFAmplifierInStruct; BoxType: Variable; Instance: H1IscCorner Instance; PLC: H1IscCorner; Task: IscCStd
V261 = LowNoiseVco_LowNoiseVcoOutStruct: LowNoiseVcoOutStruct; BoxType: Variable; Instance: H1IscCorner Instance; PLC: H1IscCorner; Task: IscCStd
V264 = DelayLogic_DelayLogicOutStruct: DelayLogicOutStruct; BoxType: Variable; Instance: H1IscCorner Instance; PLC: H1IscCorner; Task: IscCStd
V265 = DelayLogic_DelayLogicOutStructB: DelayLogicOutStruct; BoxType: Variable; Instance: H1IscCorner Instance; PLC: H1IscCorner; Task: IscCStd
V266 V267 V271 = Demodulator_DemodulatorOutStruct: DemodulatorOutStruct; BoxType: Variable; Instance: H1IscCorner Instance; PLC: H1IscCorner; Task: IscCStd
V268-V270 V280-V286 = Demodulator_DemodulatorInStruct: DemodulatorInStruct; BoxType: Variable; Instance: H1IscCorner Instance; PLC: H1IscCorner; Task: IscCStd
V287 = Demodulator_DemodulatorInStruct: DemodulatorInStruct; BoxType: Variable; Instance: H1SqzCorner Instance; PLC: H1SqzCorner; Task: SqzCStd
V288 = Demodulator_DemodulatorInStruct: DemodulatorInStruct; BoxType: Variable; Instance: H1SqzCorner Instance; PLC: H1SqzCorner; Task: SqzCFast
V293-V296 V299 = Demodulator_DemodulatorOutStruct: DemodulatorOutStruct; BoxType: Variable; Instance: H1SqzCorner Instance; PLC: H1SqzCorner; Task: SqzCStd
V680 V681 = Demodulator_DemodulatorInStructSign: DemodulatorInStruct; BoxType: Variable; Instance: H1SqzCorner Instance; PLC: H1SqzCorner; Task: SqzCStd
